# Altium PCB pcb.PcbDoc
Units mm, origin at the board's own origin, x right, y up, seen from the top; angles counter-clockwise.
Board outline 11.94 x 11.05 mm, 2 copper layers (Top Layer, Bottom Layer); 9 components, 6 nets, 43 pads, 16 vias.
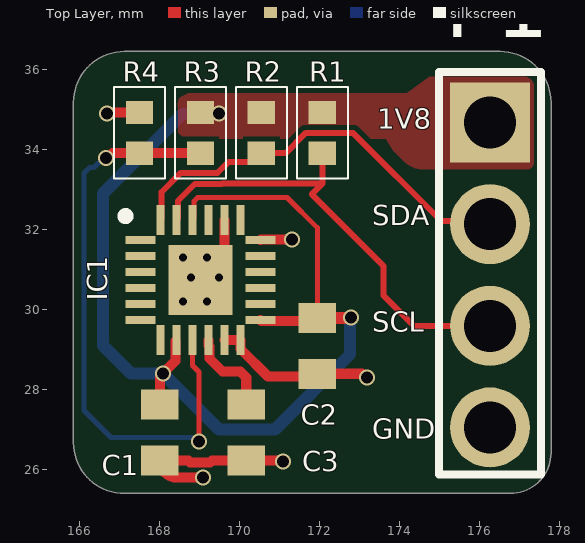
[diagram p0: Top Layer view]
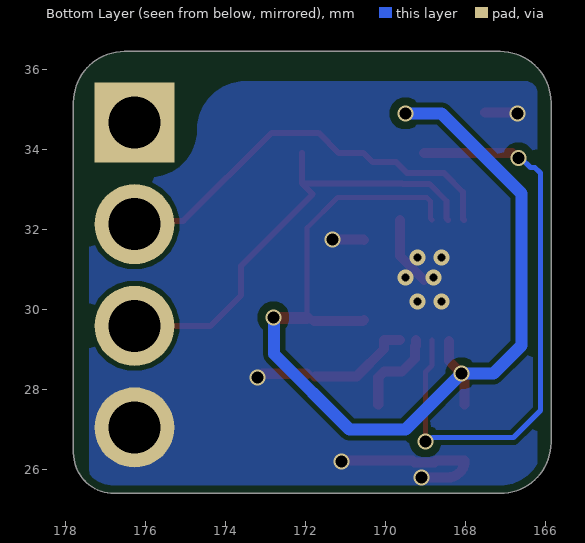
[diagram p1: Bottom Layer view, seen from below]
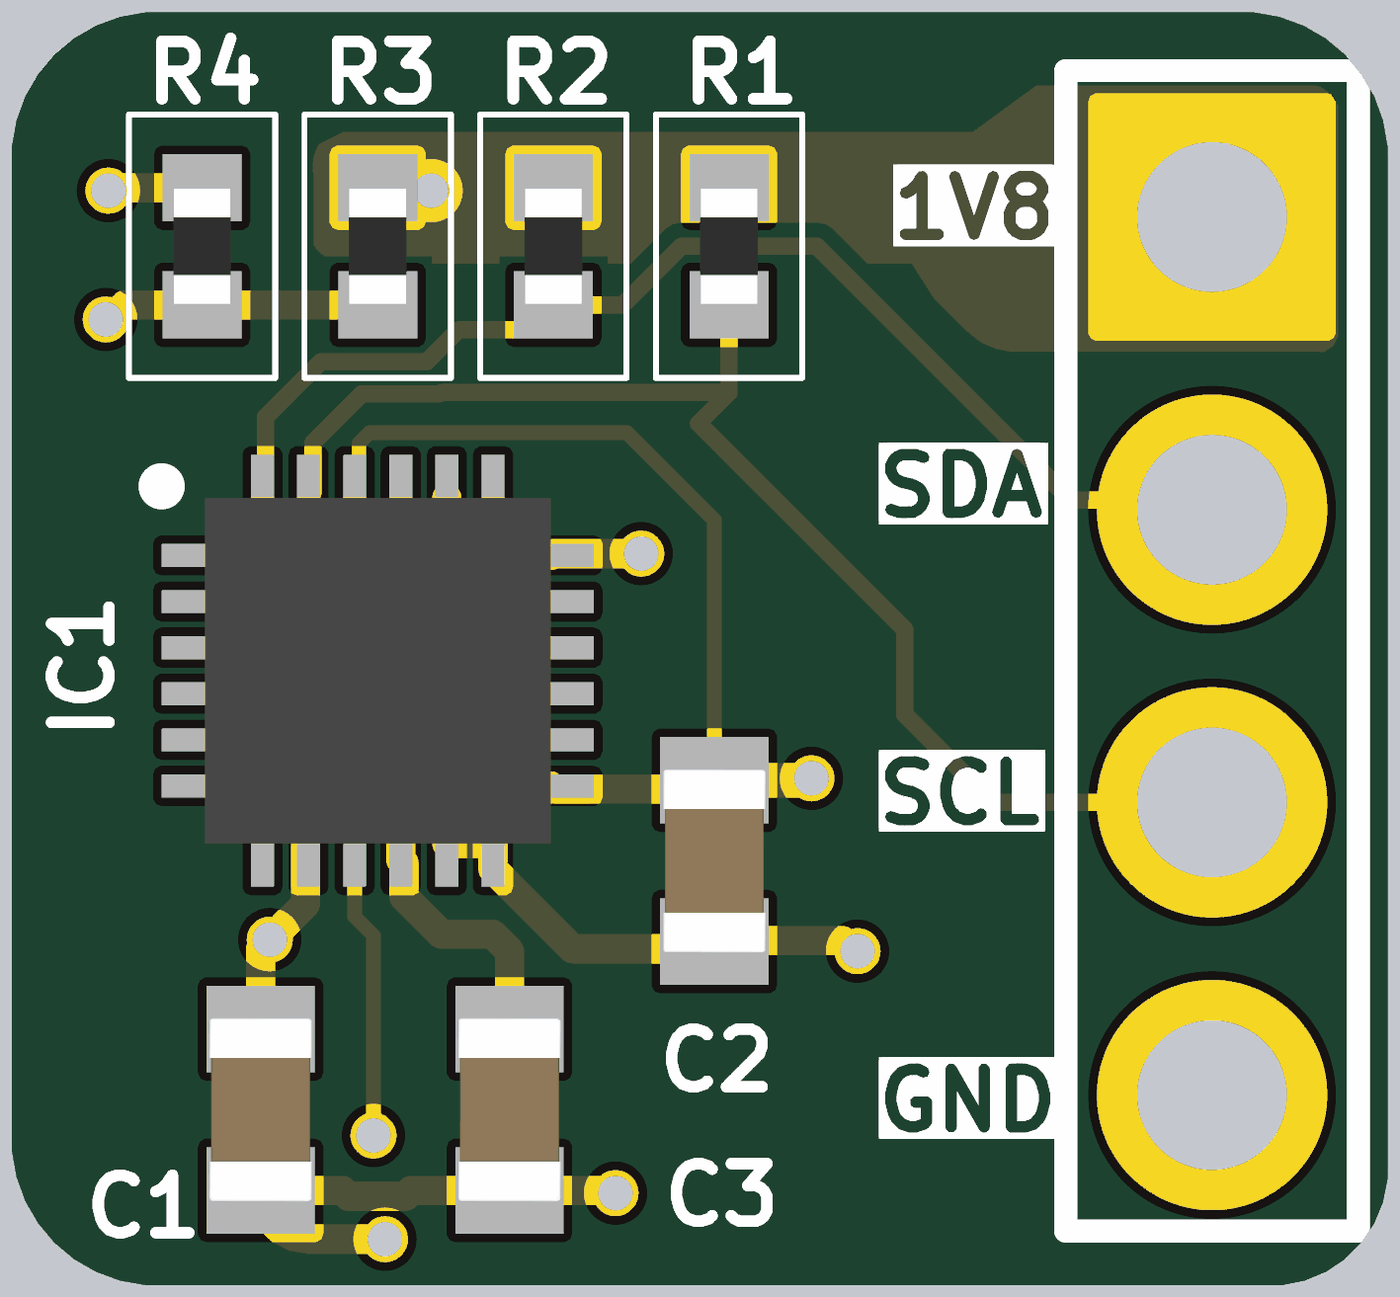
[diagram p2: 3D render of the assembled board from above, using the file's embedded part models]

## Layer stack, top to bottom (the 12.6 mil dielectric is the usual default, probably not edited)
Top Solder: solder mask 0.0102, Solder Resist, Dk 3.5
Top Layer: signal copper 0.0356
Dielectric 1: dielectric 0.32, FR-4, Dk 4.8
Bottom Layer: signal copper 0.0356
Bottom Solder: solder mask 0.0102, Solder Resist, Dk 3.5

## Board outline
165.862,26.67 ccw(c167.132,26.67) 167.132,25.4 176.784,25.4 ccw(c176.784,26.416) 177.8,26.416 177.8,35.179 ccw(c176.53,35.179) 176.53,36.449 167.132,36.449 ccw(c167.132,35.179) 165.862,35.179

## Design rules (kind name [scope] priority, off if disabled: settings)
BoardOutlineClearance [All] p1: gap=0.2 ignorepadtopadclearanceinfootprint=FALSE
Clearance [All] p1: gap=0.127 ignorepadtopadclearanceinfootprint=FALSE except(0.25: Arc-Hole Track-Hole SMDPad-Hole THPad-Hole Via-Hole Fill-Hole Poly-Hole Region-Hole Text-Hole)
ComponentClearance [All] p1: gap=0.127 collisioncheckmode=3 verticalgap=0.127 showdistances=TRUE
DiffPairsRouting [All] p1: maxlimit=0.254 minlimit=0.127 mostfreqgap=0.127 toplayer_minwidth=0.127 toplayer_maxwidth=25.4 toplayer_prefwidth=0.127 bottomlayer_minwidth=0.127 bottomlayer_maxwidth=25.4 bottomlayer_prefwidth=0.127 maxuncoupledlength=12.7
Height [All] p1: minheight=0 maxheight=1816.048 prefheight=12.7
HoleSize [All] p1: absolutevalues=TRUE maxlimit=6.3 minlimit=0.3 maxpercent=80.000 minpercent=20.000
HoleToHoleClearance [All] p1: gap=0.25 allowstackedmicrovias=FALSE
MinimumAnnularRing [All] p1: minimumring=0.076
MinimumSolderMaskSliver [All] p1: minsoldermaskwidth=0
PlaneClearance [All] p1: clearance=0.127
PlaneConnect PlaneConnectPowerPads [InPadClass('PowerPads')] p1: planeconnectstyle=Direct reliefexpansion=0.508 reliefentries=4 reliefconductorwidth=0.254 reliefairgap=0.254
PlaneConnect [All] p2: pad.planeconnectstyle=Relief pad.reliefexpansion=0.3 pad.reliefentries=4 pad.reliefconductorwidth=0.127 pad.reliefairgap=0.127 via.planeconnectstyle=Direct via.reliefexpansion=0.3 via.reliefentries=4 via.reliefconductorwidth=0.127 via.reliefairgap=0.127
PolygonConnect PolygonConnectPowerPads [All vs InNetClass('PowerPad')] p1: connectstyle=Direct reliefconductorwidth=0.254 reliefentries=4 polygonreliefangle="90 Angle" airgapwidth=0.254
PolygonConnect [All] p2: thpad.connectstyle=Relief thpad.reliefconductorwidth=0.127 thpad.reliefentries=4 thpad.polygonreliefangle="90 Angle" thpad.airgapwidth=0.127 smdpad.connectstyle=Relief smdpad.reliefconductorwidth=0.127 smdpad.reliefentries=4 smdpad.polygonreliefangle="90 Angle" smdpad.airgapwidth=0.127 via.connectstyle=Direct via.reliefconductorwidth=0.127 via.reliefentries=4 via.polygonreliefangle="90 Angle" via.airgapwidth=0.127
RoutingVias [All] p1: holewidth=0.3 width=0.6 viastyle="Through Hole" minholewidth=0.3 minwidth=0.6 maxholewidth=0.6 maxwidth=6.6
SilkToSilkClearance [All] p1: silktosilkclearance=0
SilkToSolderMaskClearance [IsPad] p1: minsilkscreentomaskgap=0.127 clearancetoexposedcopper=TRUE
SolderMaskExpansion [All] p1: expansion=0.075 istentingtop=FALSE
Width [All] p1: maxlimit=25.4 minlimit=0.127 preferedwidth=0.127 minimp=50.000000 maximp=50.000000 favimp=50.000000
20 further rules are at their usual default settings.

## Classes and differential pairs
net class PowerPad: 1V8 GND NetC3_1

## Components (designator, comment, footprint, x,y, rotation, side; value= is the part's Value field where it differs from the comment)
C1 "cap0603" CAPC1608X90N 168.021,26.924 r270 top
C2 "cap0603" CAPC1608X90N 171.958,29.083 r270 top
C3 "cap0603" CAPC1608X90N 170.18,26.924 r270 top
IC1 "ICM-20948" QFN40P300X300X105-25N-D 169.037,30.734 r0 top
P1 "Header 4" HDR1X4_DIA1.5 176.276,34.671 r270 top value=HDR4
R1 "res0402" 0402resistor 172.085,34.417 r270 top
R2 "res0402" 0402resistor 170.561,34.417 r270 top
R3 "res0402" 0402resistor 169.037,34.417 r270 top
R4 "res0402" 0402resistor 167.513,34.417 r90 top

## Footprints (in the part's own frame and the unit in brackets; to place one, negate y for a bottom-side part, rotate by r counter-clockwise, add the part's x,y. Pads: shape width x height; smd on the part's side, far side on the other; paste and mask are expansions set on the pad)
0402resistor [mil]
  rect 23x27 smd: 1(-20,0) 2(20,0)
  silkscreen extent -45,-25 45,25, body extent -20,-10 20,10, height 10
CAPC1608X90N [mm]
  rect 0.75x0.94 smd: 1(-0.7,0) 2(0.7,0)
  body extent -0.8,-0.45 0.8,0.45, height 0.8
HDR1X4_DIA1.5 [mm]
  rect 2x2 hole 1.3: 1(0,0)
  round 2 hole 1.3: 2(2.54,0) 3(5.08,0) 4(7.62,0)
  silkscreen extent -1.27,-1.27 8.8,1.27, body extent -0.5,-0.5 8.12,0.5, height 10
QFN40P300X300X105-25N-D [mm]
  rect 0.75x0.2 smd: 1(-1.5,1) 2(-1.5,0.6) 3(-1.5,0.2) 4(-1.5,-0.2) 5(-1.5,-0.6) 6(-1.5,-1) 13(1.5,-1) 14(1.5,-0.6) 15(1.5,-0.2) 16(1.5,0.2) 17(1.5,0.6) 18(1.5,1)
  rect 0.2x0.75 smd: 7(-1,-1.5) 8(-0.6,-1.5) 9(-0.2,-1.5) 10(0.2,-1.5) 11(0.6,-1.5) 12(1,-1.5) 19(1,1.5) 20(0.6,1.5) 21(0.2,1.5) 22(-0.2,1.5) 23(-0.6,1.5) 24(-1,1.5)
  rect 1.59x1.75 smd: 25(0,0)
  silkscreen extent -1.97,1.5 -1.78,1.7, body extent -1.5,-1.5 1.51,1.51, height 1

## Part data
C1 C2 C3: "Capacitor", Arrow Part Number=CL10A106KP8NNNC, Manufacturer_Name=SAMSUNG, Mouser Part Number=187-CL10A106KP8NNNC
IC1: "Integrated Circuit", Manufacturer_Name=TDK, Mouser Part Number=410-ICM-20948
P1: library part CMP-002-00093-3, "Header, 4-Pin"
R1 R2: Resistance=3k3
R3 R4: Resistance=10k

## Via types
v1: diameter 0.4, hole 0.3, Top Layer to Bottom Layer, 10 vias
v2: diameter 0.4, hole 0.2, Top Layer to Bottom Layer, 6 vias

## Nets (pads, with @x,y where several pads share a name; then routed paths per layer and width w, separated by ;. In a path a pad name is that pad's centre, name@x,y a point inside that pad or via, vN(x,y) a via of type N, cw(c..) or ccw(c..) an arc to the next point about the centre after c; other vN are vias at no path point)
1V8: C1.1 C2.1 IC1.8 IC1.13 IC1.22 P1.1 R1.1 R2.1 R3.1 | length 26.3
  Top Layer w0.127: IC1.22 168.874,32.27 168.874,32.706 168.967,32.8 171.2,32.8 171.958,32.042 C2.1
  Top Layer w0.254: C1.1 168.021,28.321 168.41,28.71 IC1.8@168.41,29.207 ; IC1.13 170.564,29.707 C2.1@171.78,29.707
  Top Layer w0.3: C2.1 172.783,29.783 v1(172.8,29.8)
  Bottom Layer w0.3: v1(169.5,34.9) 168.6,34.9 166.6,32.9 166.6,29.1 167.3,28.4 v1(168.1,28.4) 169.5,27 170.9,27 172.781,28.881 172.781,29.781 v1(172.8,29.8)
ADDRESS: IC1.9 R3.2 R4.1 | length 14.9
  Top Layer w0.127: IC1.9 168.837,28.599 169,28.436 v1(169,26.7)
  Top Layer w0.254: v1(166.677,33.782) 166.717,33.782 166.844,33.909 R4.1 R3.2
  Bottom Layer w0.127: v1(166.677,33.782) 166.603,33.782 166.372,33.551 166.266,33.551 166.125,33.41 166.125,27.475 166.8,26.8 168.826,26.8 168.926,26.7 v1(169,26.7)
GND: C1.2 C2.2 C3.2 IC1.11 IC1.12 IC1.18 IC1.20 IC1.25 P1.4 R4.2 | length 11.7
  Top Layer w0.254: v1(166.7,34.9) cw(c166.725,34.9) 166.725,34.925 R4.2 ; IC1.25 169.637,31.334 IC1.20 ; v1(169.1,25.8) 168.445,25.8 cw(c168.445,26.224) C1.2 168.731,26.224 168.782,26.173 169.278,26.173 169.329,26.224 171.076,26.224 cw(c171.076,26.2) v1(171.1,26.2) ; IC1.11 IC1.12 170.037,29.013 170.729,28.321 C2.2@171.766,28.321 ; IC1.18 170.553,31.75 v1(171.323,31.75) ; C2.2 171.967,28.392 173.069,28.392 173.16,28.3 v1(173.2,28.3)
  other v2: 168.6,30.2 169.2,30.2 168.8,30.8 169.5,30.8 168.6,31.3 169.2,31.3
NetC3_1: C3.1 IC1.10 | length 2.3
  Top Layer w0.254: IC1.10 169.237,29.095 169.264,29.068 169.264,28.773 169.589,28.448 170.031,28.448 170.18,28.299 C3.1
SCL: IC1.23 P1.3 R1.2 | length 11.7
  Top Layer w0.15: IC1.23 168.474,32.27 168.474,32.711 168.901,33.138 169.578,33.138 169.587,33.147 172.085,33.147 ; R1.2 172.085,33.147 ; P1.3 174.371,29.591 173.609,30.353 173.609,31.092 171.819,32.881 172.085,33.147
SDA: IC1.24 P1.2 R2.2 | length 10.5
  Top Layer w0.15: IC1.24 168.062,32.259 168.062,32.934 168.543,33.415 169.464,33.415 169.741,33.692 170.328,33.692 170.545,33.909 171.164,33.909 171.672,34.417 172.847,34.417 175.051,32.213 176.194,32.213 P1.2
pads on no net: IC1.1 IC1.2 IC1.3 IC1.4 IC1.5 IC1.6 IC1.7 IC1.14 IC1.15 IC1.16 IC1.17 IC1.19 IC1.21

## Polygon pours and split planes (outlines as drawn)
1V8 on Top Layer "1V8_L01_P000" (solid, pour order 0): 174.579,33.504 cw(c174.578,34.117) 174.145,33.684 173.858,33.97 173.671,34.266 168.789,34.266 cw(c168.789,34.699) 168.483,34.393 168.483,35.028 cw(c168.841,35.111) 168.529,35.306 168.737,35.409 174.198,35.409 174.752,35.814 177.165,35.814 cw(c177.102,35.543) 177.372,35.479 177.373,33.684 cw(c177.182,33.683) 177.119,33.504
GND on Bottom Layer "GND_L02_P002" (solid, pour order 2): 177.4,26 177.4,33.3 175.9,33.3 cw(c175.9,34.5) 174.7,34.5 ccw(c173.5,34.5) 173.5,35.7 166.5,35.7 ccw(c166.5,35.4) 166.2,35.4 166.2,26.1 ccw(c166.8,26.1) 166.8,25.5 177.3,25.5 ccw(c177.3,25.7) 177.5,25.7 177.5,26

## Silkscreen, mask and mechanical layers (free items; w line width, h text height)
Top Overlay:
  text "1V8" at 173.455,34.517 h0.5
  text "SDA" at 173.328,32.104 h0.5
  text "SCL" at 173.328,29.437 h0.5
  text "GND" at 173.328,26.77 h0.5
Mechanical 13:
  the board outline again, w0.102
